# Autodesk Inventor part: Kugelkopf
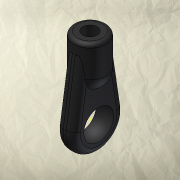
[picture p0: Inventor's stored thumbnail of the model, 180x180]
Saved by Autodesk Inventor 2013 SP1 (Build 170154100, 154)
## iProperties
Created: 2012-02
Part Number: Kugelkopf
Material: Allgemein
Document SubType Name: Modeling
Designer: WH
Density: 1 g/cm^3
ipwModelExtentsX: 4.4
ipwModelExtentsY: 7
ipwModelExtentsZ: 18.5
ipwMass: 0.0
ipwArea: 0 m^2
ipwVolume: 0
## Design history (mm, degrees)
feature "Basis1"
workplane "Arbeitsebene1"
feature "Fläche verschieben1" dims "d1" = 4.5
feature "Fläche verschieben2" dims "d2" = 4.5
workpoint "Arbeitspunkt1"
  workaxis "Arbeitsachse1"
node "линк под шарик"
other parameters: "d0" = -4.5
